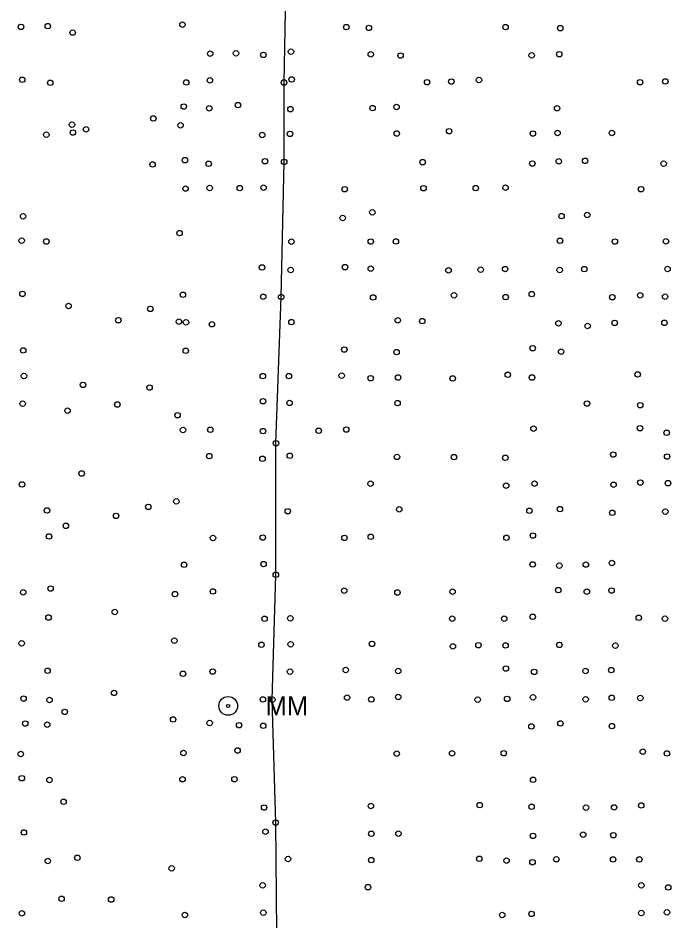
# Model space of a CAD drawing. Extents: x 20503438 to 20508873, y 7964251 to 7984667.
# Drawn here: x 20506637 to 20506876.4, y 7967040.5 to 7967371.4 of the extents above; entities that cross this region are included whole.
import ezdxf

# ---------------------------------------------------------------- set-up
doc = ezdxf.new("R2010")
doc.units = 0
for name, color, linetype in [('SurDrainageArrowUp', 7, 'Continuous'), ('SurRoadPoints', 7, 'Continuous'), ('SurSurveyPoints', 7, 'Continuous')]:
    doc.layers.add(name, color=color, linetype=linetype)

msp = doc.modelspace()

# ---------------------------------------------------------------- linework, layer by layer
at = {"layer": 'SurDrainageArrowUp'}
msp.add_lwpolyline([(20506725.56, 7966682.41), (20506728.02, 7966733.71), (20506727.82, 7966756.1), (20506729.96, 7966778.17), (20506730.53, 7966829.65), (20506730.14, 7966879.31), (20506729.13, 7966925.42), (20506730.94, 7966976.24), (20506732.01, 7967022.84), (20506731.44, 7967076.53), (20506730.2, 7967121.55), (20506731.5, 7967167.33), (20506731.55, 7967215.54), (20506733.45, 7967269.12), (20506734.55, 7967318.67), (20506734.51, 7967347.75), (20506735.53, 7967399.62)], dxfattribs=at)
at = {"layer": 'SurRoadPoints'}
for radius in [3.43, 0.571]:
    msp.add_circle((20506714.03, 7967119.27), radius, dxfattribs=at)
at = {"layer": 'SurSurveyPoints'}
for centre in [(20506638.03, 7967368.12), (20506647.87, 7967368.43), (20506697.25, 7967368.96), (20506757.35, 7967368.06), (20506765.61, 7967367.77), (20506815.76, 7967368.04), (20506835.85, 7967367.67), (20506656.99, 7967366.04), (20506707.42, 7967358.31), (20506716.89, 7967358.45), (20506726.9, 7967357.86), (20506737.05, 7967359.06), (20506766.33, 7967358.07), (20506825.33, 7967357.72), (20506835.45, 7967358.12), (20506777.24, 7967357.62), (20506638.5, 7967348.76), (20506698.62, 7967347.76), (20506707.32, 7967348.53), (20506734.51, 7967347.75), (20506737.29, 7967348.86), (20506786.99, 7967347.86), (20506795.87, 7967348.1), (20506806, 7967348.66), (20506865.09, 7967347.85), (20506874.35, 7967348.14), (20506648.74, 7967347.66), (20506697.74, 7967338.95), (20506707.06, 7967338.27), (20506717.63, 7967339.46), (20506736.85, 7967337.98), (20506766.96, 7967338.38), (20506775.77, 7967338.78), (20506834.66, 7967338.27), (20506686.56, 7967334.59), (20506656.73, 7967332.31), (20506696.56, 7967332.07), (20506647.32, 7967328.64), (20506657.05, 7967329.41), (20506661.91, 7967330.58), (20506726.5, 7967328.49), (20506736.68, 7967328.93), (20506775.84, 7967329.06), (20506795.06, 7967329.89), (20506825.76, 7967329.04), (20506834.81, 7967329.24), (20506854.74, 7967329.23), (20506698.18, 7967319.29), (20506706.86, 7967317.96), (20506727.53, 7967318.89), (20506734.55, 7967318.67), (20506785.37, 7967318.56), (20506825.55, 7967318.04), (20506835.28, 7967318.88), (20506844.91, 7967319.05), (20506873.72, 7967318.01), (20506686.29, 7967317.73), (20506698.38, 7967308.87), (20506707.21, 7967309.07), (20506718.27, 7967309.04), (20506726.98, 7967309.2), (20506756.75, 7967308.65), (20506785.65, 7967309), (20506804.84, 7967309.06), (20506815.76, 7967309.2), (20506865.44, 7967308.64), (20506638.79, 7967298.72), (20506756.01, 7967298.11), (20506766.87, 7967300.19), (20506836.3, 7967298.79), (20506845.71, 7967299.19), (20506696.19, 7967292.57), (20506638.27, 7967289.78), (20506647.32, 7967289.48), (20506737.23, 7967289.4), (20506766.31, 7967289.45), (20506775.53, 7967289.51), (20506835.7, 7967289.74), (20506855.84, 7967289.46), (20506874.56, 7967289.53), (20506726.41, 7967279.98), (20506736.93, 7967279.05), (20506756.87, 7967280.08), (20506766.33, 7967279.54), (20506794.82, 7967278.9), (20506806.62, 7967279.18), (20506815.58, 7967279.38), (20506835.59, 7967279.02), (20506844.64, 7967279.37), (20506875.18, 7967279.41), (20506638.56, 7967270.29), (20506697.4, 7967269.95), (20506726.88, 7967269.24), (20506733.45, 7967269.12), (20506767.19, 7967268.99), (20506796.85, 7967269.77), (20506815.79, 7967269.11), (20506825.37, 7967270.19), (20506854.93, 7967269.06), (20506865.15, 7967269.77), (20506874.25, 7967269.27), (20506655.49, 7967265.84), (20506685.47, 7967264.79), (20506673.75, 7967260.63), (20506695.95, 7967260.1), (20506698.54, 7967259.85), (20506708.03, 7967259.15), (20506737.22, 7967259.93), (20506776.23, 7967260.59), (20506785.19, 7967260.3), (20506835.16, 7967259.51), (20506845.84, 7967258.53), (20506855.75, 7967259.66), (20506874.01, 7967259.67), (20506638.85, 7967249.56), (20506698.48, 7967249.44), (20506756.61, 7967249.88), (20506775.77, 7967248.94), (20506825.7, 7967250.37), (20506836.12, 7967249.09), (20506639.12, 7967240.21), (20506726.73, 7967240.16), (20506736.28, 7967240.14), (20506755.66, 7967240.3), (20506766.29, 7967239.38), (20506776.35, 7967239.64), (20506796.34, 7967239.28), (20506816.55, 7967240.65), (20506825.46, 7967239.64), (20506864.19, 7967240.77), (20506660.77, 7967236.93), (20506685.18, 7967235.97), (20506638.64, 7967230.06), (20506673.38, 7967229.74), (20506726.8, 7967230.94), (20506736.53, 7967230.32), (20506776.15, 7967230.26), (20506845.62, 7967230.1), (20506865.15, 7967229.49), (20506655.1, 7967227.49), (20506695.47, 7967225.81), (20506697.45, 7967220.4), (20506707.48, 7967220.48), (20506726.79, 7967219.99), (20506747.2, 7967220.12), (20506757.33, 7967220.56), (20506826, 7967220.87), (20506865.06, 7967221.06), (20506874.85, 7967219.37), (20506731.55, 7967215.54), (20506707.1, 7967210.83), (20506726.61, 7967209.84), (20506736.62, 7967210.94), (20506775.95, 7967210.53), (20506796.86, 7967210.45), (20506815.65, 7967210.21), (20506855.25, 7967211.4), (20506875, 7967210.67), (20506660.3, 7967204.46), (20506638.41, 7967200.46), (20506766.25, 7967200.74), (20506815.97, 7967199.99), (20506826.39, 7967200.73), (20506855.37, 7967200.34), (20506865.19, 7967201.15), (20506875.31, 7967200.91), (20506695, 7967194.27), (20506647.58, 7967190.91), (20506672.93, 7967188.92), (20506684.74, 7967192.21), (20506735.86, 7967190.63), (20506776.75, 7967191.32), (20506824.51, 7967190.8), (20506835.69, 7967191.42), (20506854.87, 7967190.07), (20506874.36, 7967190.47), (20506654.49, 7967185.28), (20506648.31, 7967181.39), (20506708.44, 7967180.83), (20506726.71, 7967180.98), (20506756.66, 7967180.85), (20506766.32, 7967181.26), (20506816.08, 7967180.9), (20506825.76, 7967181.72), (20506697.87, 7967171.02), (20506727.01, 7967171.26), (20506825.7, 7967171.14), (20506835.45, 7967170.67), (20506845.19, 7967171.07), (20506854.74, 7967171.68), (20506731.5, 7967167.33), (20506638.85, 7967160.9), (20506648.89, 7967162.3), (20506694.51, 7967160.25), (20506708.4, 7967161.23), (20506756.57, 7967161.54), (20506776.11, 7967160.85), (20506796.31, 7967161.15), (20506835.09, 7967161.72), (20506845.56, 7967161.16), (20506854.63, 7967161.57), (20506672.41, 7967153.72), (20506648.12, 7967151.68), (20506727.36, 7967151.21), (20506736.83, 7967151.4), (20506796.19, 7967151.25), (20506815.26, 7967151.26), (20506825.68, 7967151.94), (20506864.62, 7967151.58), (20506874.23, 7967151.26), (20506694.26, 7967143.18), (20506638.26, 7967142.2), (20506726.22, 7967141.68), (20506736.93, 7967141.85), (20506766.76, 7967142.01), (20506796.42, 7967141.11), (20506805.8, 7967141.53), (20506815.74, 7967141.45), (20506835.48, 7967141.66), (20506856.02, 7967141.35), (20506815.87, 7967132.98), (20506647.76, 7967132.17), (20506697.45, 7967131.06), (20506708.33, 7967131.86), (20506736.7, 7967131.84), (20506757.13, 7967132.44), (20506776.4, 7967132.09), (20506826.24, 7967131.74), (20506845.08, 7967132.06), (20506854.5, 7967132.39), (20506672.19, 7967124.04), (20506638.96, 7967121.99), (20506648.5, 7967121.46), (20506726.76, 7967121.64), (20506730.2, 7967121.55), (20506757.64, 7967122.31), (20506766.52, 7967121.65), (20506776.39, 7967122.54), (20506805.54, 7967121.56), (20506816.34, 7967121.87), (20506825.83, 7967122.42), (20506845.11, 7967121.69), (20506854.69, 7967122.27), (20506865.18, 7967122.17), (20506654.08, 7967117.08), (20506639.58, 7967112.82), (20506693.83, 7967114.32), (20506707.22, 7967113.04), (20506835.88, 7967112.85), (20506647.65, 7967112.41), (20506718.01, 7967112.22), (20506726.88, 7967112), (20506825.23, 7967111.77), (20506854.74, 7967111.87), (20506717.47, 7967102.94), (20506637.95, 7967101.67), (20506697.61, 7967102.04), (20506775.84, 7967101.77), (20506796.14, 7967101.89), (20506815.08, 7967101.93), (20506866.08, 7967102.53), (20506874.91, 7967101.87), (20506638.34, 7967092.79), (20506648.46, 7967092.13), (20506697.27, 7967092.4), (20506716.32, 7967092.43), (20506825.86, 7967092.21), (20506653.65, 7967084.14), (20506727.18, 7967082.04), (20506766.36, 7967082.6), (20506806.27, 7967082.93), (20506825.29, 7967082.32), (20506845.24, 7967081.99), (20506855.55, 7967082.09), (20506865.5, 7967082.8), (20506731.44, 7967076.53), (20506727.71, 7967073.18), (20506639.11, 7967072.92), (20506766.5, 7967072.43), (20506776.46, 7967072.45), (20506825.83, 7967071.65), (20506844.21, 7967072.09), (20506855.26, 7967071.9), (20506658.69, 7967063.62), (20506735.98, 7967063.2), (20506806.12, 7967063.25), (20506647.85, 7967062.46), (20506766.48, 7967062.76), (20506816.12, 7967062.55), (20506825.63, 7967062.01), (20506834.37, 7967063.08), (20506855.21, 7967063.03), (20506864.82, 7967063.02), (20506693.31, 7967059.76), (20506726.68, 7967053.54), (20506865.56, 7967053.55), (20506765.31, 7967052.86), (20506875.41, 7967052.76), (20506652.91, 7967048.59), (20506671.1, 7967048.34), (20506726.9, 7967043.53), (20506865.53, 7967043.4), (20506874.98, 7967043.63), (20506638.35, 7967043.28), (20506698.15, 7967042.67), (20506814.54, 7967042.67), (20506825.3, 7967043.07)]:
    msp.add_circle(centre, 1, dxfattribs=at)

# ---------------------------------------------------------------- texts
at = {"layer": 'SurRoadPoints'}
msp.add_text('MM', height=6.995, rotation=360, dxfattribs=at).set_placement((20506727.74, 7967115.77))

doc.saveas('drawing.dxf')
